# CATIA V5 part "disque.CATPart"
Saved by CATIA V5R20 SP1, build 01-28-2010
Part number: disque1.1
Bounding box of the stored display mesh (mm): x 67.459 to 92.541, y 0 to 10, z 87.65 to 112.35
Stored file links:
  E:\EDELI\gcausse\Edeli_2012_233_gcausse\disque.CATPart
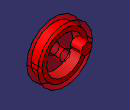
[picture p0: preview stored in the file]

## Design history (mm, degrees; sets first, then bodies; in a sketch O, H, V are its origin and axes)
Body1 (main body)
  DatumSurface1
  Sketch1 on face of DatumSurface1, origin (0, 5, 0), H (1, 0, 0), V (0, 0, 1)
    circle A1 centre (80, 100) radius 8.541
    circle A2 centre (80, 100) radius 2.5
    radius A1 = 8.541
    radius A2 = 2.5
  Pad1: profile Sketch1, direction (0, -1, 0), length 5
Body2
  Sketch2 on start face of Pad1, origin (0, 5, 0), H (-1, 0, 0), V (0, 0, 1)
    circle A1 centre (-80, 100) radius 10.541
    circle A2 centre (-80, 100) radius 8.541
    radius A2 = 8.541
    radius A1 = 10.541
  Pad2: profile Sketch2, direction (0, -1, 0), length 5
  Sketch3 on start face of Pad1, origin (0, 5, 0), H (-1, 0, 0), V (0, 0, 1)
Body3
  Sketch4 on start face of Pad1, origin (0, 5, 0), H (-1, 0, 0), V (0, 0, 1)
    circle A1 centre (-80, 100) radius 12.541
    circle A2 centre (-80, 100) radius 10.541
    radius A2 = 10.541
    radius A1 = 12.541
  Pad3: profile Sketch4, direction (0, -1, 0), length 5
  DatumCurve1
  Sketch5 on start face of Pad1, origin (0, 5, 0), H (-1, 0, 0), V (0, 0, 1)
    circle A1 centre (-75.0807, 102.4597) radius 2.5
    point P1 (-75.0807, 102.4597)
    reference projected circle E1 centre (-80, 100) radius 2.5 from edge of DatumCurve1
    radius A1 = 2.5
    distance P1 E1 = 3
  Pad4: profile Sketch5, direction (0, 1, 0), length 5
